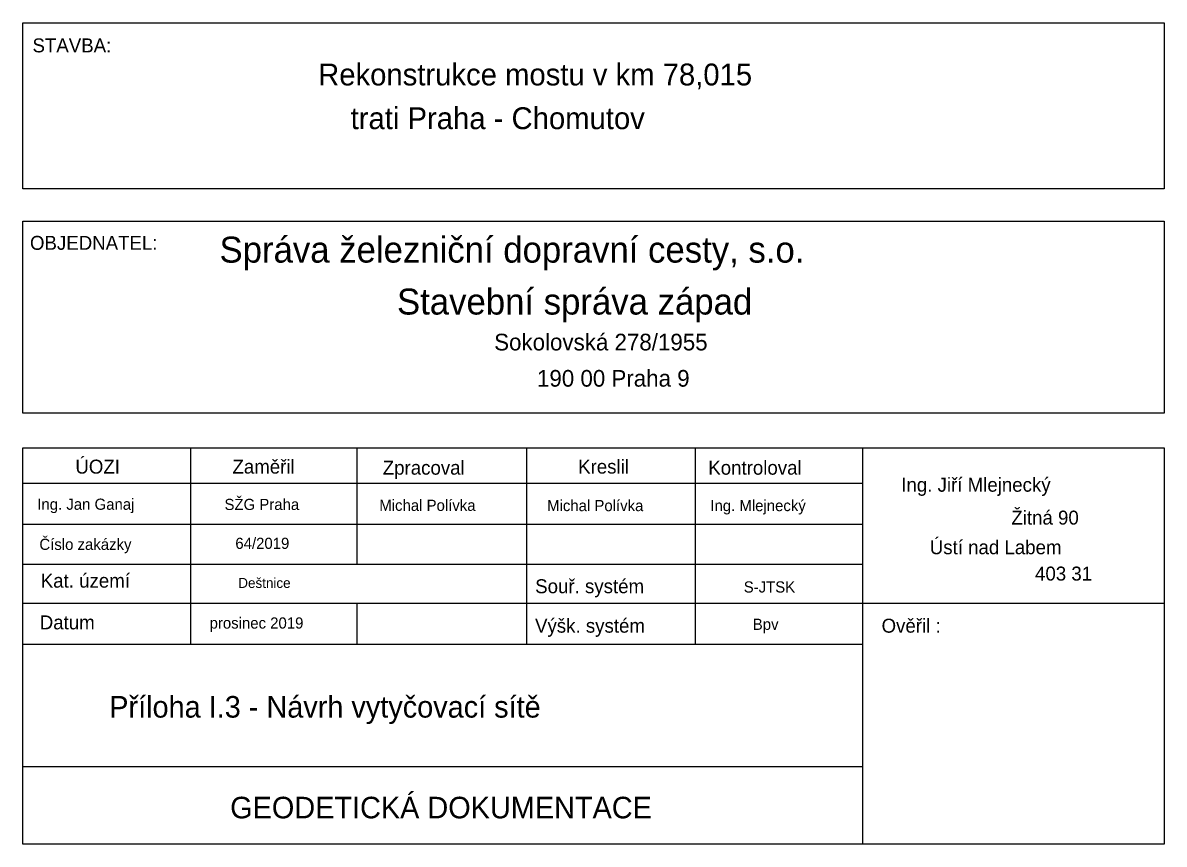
# Model space of a CAD drawing. Extents: x -879530 to -879371, y -1019242 to -1019127.
import ezdxf

# ---------------------------------------------------------------- set-up
doc = ezdxf.new("R2010")
doc.units = 0
doc.layers.add('LEGENDA', color=7, linetype='Continuous')
doc.layers.add('tabulka', color=7, linetype='Continuous')

msp = doc.modelspace()

# ---------------------------------------------------------------- linework, layer by layer
at = {"layer": 'tabulka'}
for p, q in [((-879530.09, -1019186.45), (-879371.44, -1019186.45)), ((-879506.8, -1019186.45), (-879506.8, -1019213.77)), ((-879483.66, -1019186.45), (-879483.66, -1019202.65)), ((-879460.06, -1019186.45), (-879460.06, -1019213.77)), ((-879436.61, -1019186.45), (-879436.61, -1019213.77)), ((-879413.31, -1019241.58), (-879413.31, -1019186.45)), ((-879530.09, -1019191.36), (-879413.31, -1019191.36)), ((-879530.09, -1019197.07), (-879413.31, -1019197.07)), ((-879530.09, -1019202.65), (-879413.31, -1019202.65)), ((-879530.09, -1019208.07), (-879371.44, -1019208.07)), ((-879483.66, -1019208.07), (-879483.66, -1019213.77)), ((-879530.09, -1019213.77), (-879413.31, -1019213.77)), ((-879530.09, -1019230.76), (-879413.31, -1019230.76))]:
    msp.add_line(p, q, dxfattribs=at)
for points in [[(-879530.09, -1019127.36), (-879371.44, -1019127.36), (-879371.44, -1019150.43), (-879530.09, -1019150.43)], [(-879530.09, -1019154.95), (-879371.44, -1019154.95), (-879371.44, -1019181.64), (-879530.09, -1019181.64)]]:
    msp.add_lwpolyline(points, close=True, dxfattribs=at)
msp.add_lwpolyline([(-879371.44, -1019186.45), (-879371.44, -1019241.58), (-879530.09, -1019241.58), (-879530.09, -1019186.45)], dxfattribs=at)

# ---------------------------------------------------------------- texts
at = {"layer": 'LEGENDA'}
for s, p in [('Rekonstrukce mostu v km 78,015', (-879489.04, -1019136.07)), ('    trati Praha - Chomutov', (-879489.04, -1019142.15))]:
    msp.add_text(s, height=3.04, dxfattribs=at).set_placement(p)
at = {"layer": 'tabulka'}
for s, height, p in [('STAVBA:', 1.94, (-879528.75, -1019131.47)), ('OBJEDNATEL:', 1.94, (-879529.1, -1019158.93)), ('Správa železniční dopravní cesty, s.o.', 3.61, (-879502.75, -1019160.71)), ('Stavební správa západ', 3.61, (-879478.08, -1019167.93)), ('Sokolovská 278/1955', 2.32, (-879464.57, -1019172.92)), ('190 00 Praha 9', 2.32, (-879458.62, -1019177.96)), ('ÚOZI', 1.94, (-879522.79, -1019190.05)), ('Zaměřil', 1.94, (-879500.95, -1019190.05)), ('Zpracoval', 1.94, (-879480.06, -1019190.2)), ('Kreslil', 1.94, (-879452.9, -1019190.05)), ('Kontroloval', 1.94, (-879434.81, -1019190.2)), ('Ing. Jiří Mlejnecký', 1.94, (-879407.98, -1019192.57)), ('Ing. Jan Ganaj', 1.552, (-879528.08, -1019195.08)), ('SŽG Praha', 1.552, (-879502.06, -1019195.11)), ('Michal Polívka', 1.552, (-879480.54, -1019195.23)), ('Michal Polívka', 1.552, (-879457.21, -1019195.27)), ('Ing. Mlejnecký', 1.552, (-879434.52, -1019195.27)), ('Žitná 90', 1.94, (-879392.68, -1019197.14)), ('Číslo zakázky', 1.552, (-879527.79, -1019200.66)), ('64/2019', 1.552, (-879500.55, -1019200.52)), ('Ústí nad Labem', 1.94, (-879404.02, -1019201.26)), ('403 31', 1.94, (-879389.39, -1019204.92)), ('Kat. území', 1.94, (-879527.6, -1019205.91)), ('Deštnice', 1.397, (-879500.14, -1019205.95)), ('Souř. systém', 1.94, (-879458.87, -1019206.68)), ('S-JTSK', 1.552, (-879429.88, -1019206.59)), ('Datum', 1.94, (-879527.74, -1019211.71)), ('prosinec 2019', 1.552, (-879504.13, -1019211.6)), ('Výšk. systém', 1.94, (-879458.89, -1019212.17)), ('Bpv', 1.552, (-879428.62, -1019211.78)), ('Ověřil :', 1.94, (-879410.72, -1019212.17)), ('Příloha I.3 - Návrh vytyčovací sítě', 3, (-879518.08, -1019223.98)), ('GEODETICKÁ DOKUMENTACE ', 3, (-879501.27, -1019237.99))]:
    msp.add_text(s, height=height, dxfattribs=at).set_placement(p)

doc.saveas('drawing.dxf')
